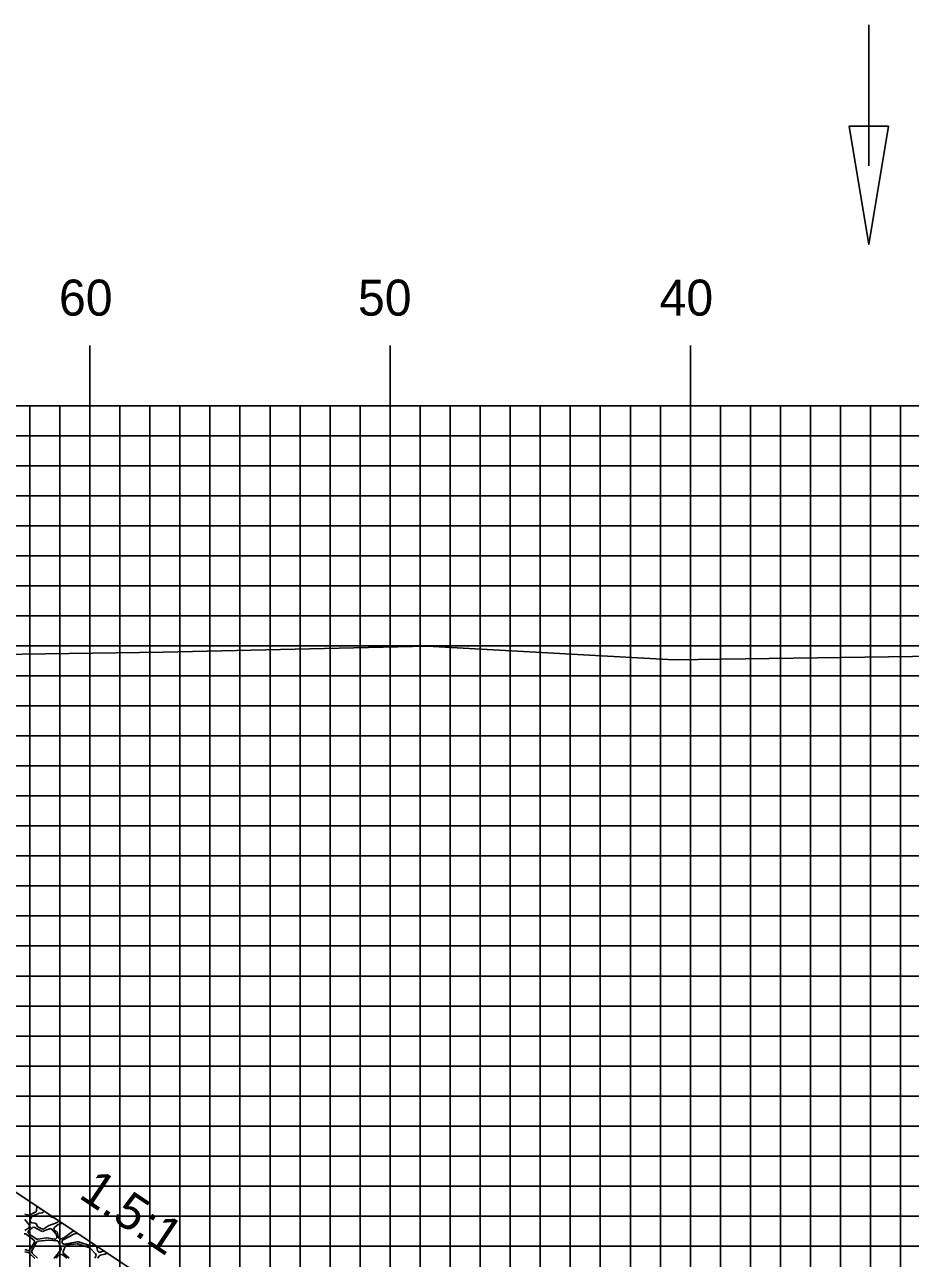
# Model space of a CAD drawing. Extents: x 1770055 to 1770398, y 442591 to 442811.
# Drawn here: x 1770158.36 to 1770187.85, y 442635.26 to 442676.36 of the extents above; entities that cross this region are included whole.
import ezdxf

# ---------------------------------------------------------------- set-up
doc = ezdxf.new("R2010")
doc.units = 0
for name, color, linetype in [('ANNOTATION', 7, 'Continuous'), ('D_Drainage_Ditch_Line', 7, 'Continuous'), ('D_Roadway_Centerline', 7, 'Continuous'), ('D_Roadway_SlopeLines', 7, 'Continuous'), ('GRUBBING IN FILL', 7, 'Continuous'), ('H_V ANNOTATION', 7, 'Continuous'), ('MAJOR', 7, 'Continuous'), ('MINOR', 7, 'Continuous'), ('S_Roadway_Centerline', 7, 'Continuous')]:
    doc.layers.add(name, color=color, linetype=linetype)

msp = doc.modelspace()

# ---------------------------------------------------------------- linework, layer by layer
at = {"layer": 'D_Drainage_Ditch_Line'}
msp.add_line((1770186.466, 442671.659), (1770186.466, 442676.358), dxfattribs=at)
msp.add_lwpolyline([(1770187.122, 442672.972), (1770185.81, 442672.972), (1770186.466, 442669.035)], close=True, dxfattribs=at)
at = {"layer": 'D_Roadway_Centerline'}
msp.add_lwpolyline([(1770129.303, 442654.95), (1770129.452, 442654.939), (1770130.553, 442654.854), (1770130.77, 442654.801), (1770131.803, 442654.548), (1770132.952, 442654.073), (1770133.053, 442654.031), (1770134.303, 442653.303), (1770134.304, 442653.302), (1770162.371, 442634.591), (1770186.354, 442618.602), (1770187.025, 442618.77), (1770190.354, 442619.602), (1770200.03, 442622.022), (1770200.528, 442622.146), (1770208.528, 442622.466), (1770220.528, 442622.706), (1770227.293, 442622.571), (1770232.528, 442622.466), (1770240.528, 442622.146), (1770241.369, 442621.936), (1770250.701, 442619.602), (1770250.702, 442619.602), (1770253.913, 442618.8)], dxfattribs=at)
at = {"layer": 'D_Roadway_SlopeLines'}
msp.add_lwpolyline([(1770186.354, 442618.602), (1770134.303, 442653.303), (1770133.053, 442654.031), (1770131.803, 442654.548), (1770130.553, 442654.854), (1770129.303, 442654.95)], dxfattribs=at)
at = {"layer": 'GRUBBING IN FILL'}
for p, q in [((1770158.76, 442636.998), (1770158.747, 442636.851)), ((1770158.491, 442636.7), (1770158.358, 442636.735)), ((1770158.358, 442636.556), (1770158.504, 442636.378)), ((1770158.711, 442636.797), (1770158.541, 442636.706)), ((1770158.543, 442636.537), (1770158.589, 442636.642)), ((1770158.625, 442636.677), (1770158.818, 442636.758)), ((1770158.836, 442636.762), (1770158.927, 442636.774)), ((1770158.871, 442636.913), (1770158.864, 442636.929)), ((1770158.922, 442636.891), (1770158.9, 442636.892)), ((1770158.962, 442636.789), (1770159, 442636.822)), ((1770159.2, 442636.705), (1770159.205, 442636.68)), ((1770159.258, 442636.628), (1770159.342, 442636.61)), ((1770158.492, 442636.28), (1770158.358, 442636.182)), ((1770158.498, 442636.184), (1770158.624, 442636.286)), ((1770158.701, 442636.431), (1770158.599, 442636.442)), ((1770158.701, 442636.292), (1770158.918, 442636.166)), ((1770158.762, 442636.366), (1770158.761, 442636.371)), ((1770158.931, 442636.244), (1770158.798, 442636.314)), ((1770158.978, 442636.162), (1770159.188, 442636.245)), ((1770159.159, 442636.349), (1770158.999, 442636.247)), ((1770159.44, 442636.45), (1770159.173, 442636.356)), ((1770159.265, 442636.226), (1770159.403, 442636.065)), ((1770159.355, 442636.287), (1770159.44, 442636.364)), ((1770159.412, 442636.153), (1770159.369, 442636.176)), ((1770159.451, 442636.371), (1770159.609, 442636.432)), ((1770159.95, 442636.15), (1770159.688, 442635.953)), ((1770160.012, 442636.163), (1770159.993, 442636.164)), ((1770158.403, 442636.066), (1770158.658, 442635.869)), ((1770158.744, 442635.908), (1770158.502, 442636.075)), ((1770158.676, 442635.781), (1770158.544, 442635.554)), ((1770158.749, 442635.799), (1770158.6, 442635.507)), ((1770159.081, 442635.937), (1770158.792, 442635.897)), ((1770159.143, 442635.87), (1770158.803, 442635.836)), ((1770159.35, 442635.899), (1770159.1, 442635.937)), ((1770159.441, 442635.837), (1770159.158, 442635.869)), ((1770159.418, 442636.033), (1770159.428, 442635.979)), ((1770159.466, 442636.015), (1770159.447, 442636.107)), ((1770159.487, 442635.955), (1770159.469, 442636.005)), ((1770159.567, 442635.612), (1770159.497, 442635.794)), ((1770159.667, 442635.942), (1770159.571, 442635.912)), ((1770159.603, 442635.802), (1770159.609, 442635.779)), ((1770159.991, 442636.068), (1770159.637, 442635.881)), ((1770159.687, 442635.73), (1770160.115, 442635.807)), ((1770160.101, 442635.743), (1770159.762, 442635.704)), ((1770160.131, 442636.085), (1770160.017, 442636.075)), ((1770160.523, 442635.604), (1770160.131, 442635.739)), ((1770160.147, 442635.805), (1770160.561, 442635.681)), ((1770160.647, 442635.733), (1770160.649, 442635.739)), ((1770158.466, 442635.522), (1770158.358, 442635.553)), ((1770158.358, 442635.471), (1770158.475, 442635.451)), ((1770158.509, 442635.434), (1770158.686, 442635.269)), ((1770158.612, 442635.427), (1770158.78, 442635.26)), ((1770159.352, 442635.28), (1770159.557, 442635.545)), ((1770159.465, 442635.341), (1770159.41, 442635.26)), ((1770159.567, 442635.387), (1770159.502, 442635.368)), ((1770159.762, 442635.26), (1770159.632, 442635.373)), ((1770159.705, 442635.659), (1770159.644, 442635.491)), ((1770159.663, 442635.417), (1770159.839, 442635.26)), ((1770160.718, 442635.409), (1770160.55, 442635.586)), ((1770160.699, 442635.26), (1770160.731, 442635.335)), ((1770160.787, 442635.518), (1770160.753, 442635.669)), ((1770160.787, 442635.26), (1770160.849, 442635.339)), ((1770161.001, 442635.504), (1770160.872, 442635.467)), ((1770160.884, 442635.363), (1770161.026, 442635.401)), ((1770161.031, 442635.403), (1770161.11, 442635.431)), ((1770159.329, 442635.26), (1770159.34, 442635.269))]:
    msp.add_line(p, q, dxfattribs=at)
for centre, major_axis, start_param, end_param in [((1770158.509, 442636.766), (0, -0.0683), 6.025862, 6.773143), ((1770158.652, 442636.614), (0, 0.0683), 0.394791, 1.157466), ((1770158.679, 442636.857), (0, -0.0683), 0.489957, 1.480136), ((1770158.844, 442636.694), (0, 0.0683), 0.124355, 0.394791), ((1770158.902, 442636.926), (0, -0.0342), 5.10718, 6.225111), ((1770158.918, 442636.841), (0, -0.0683), 0.124355, 0.704494), ((1770159.044, 442636.77), (0, 0.0683), 0.484122, 0.704494), ((1770159.272, 442636.695), (0, -0.0683), 4.928939, 6.08014), ((1770158.541, 442636.131), (0, -0.0683), 3.820255, 5.679955), ((1770158.451, 442636.335), (0, 0.0683), 3.773738, 5.401291), ((1770158.606, 442636.51), (0, -0.0683), 4.299059, 6.17752), ((1770158.667, 442636.233), (0, 0.0683), 5.75839, 6.961848), ((1770158.693, 442636.363), (0, 0.0683), 4.831818, 6.17752), ((1770158.829, 442636.374), (0, -0.0683), 4.831818, 5.797153), ((1770158.953, 442636.225), (0, -0.0683), 5.75839, 6.659146), ((1770158.962, 442636.304), (0, -0.0683), 5.797153, 6.853569), ((1770159.196, 442636.292), (0, 0.0683), 0.338698, 0.570383), ((1770159.213, 442636.181), (0, 0.0683), 5.421015, 6.659146), ((1770159.401, 442636.236), (0, -0.0683), 3.878249, 5.800672), ((1770159.381, 442636.093), (0, 0.0683), 4.915434, 5.800672), ((1770159.417, 442636.515), (0, 0.0683), 3.480291, 4.716793), ((1770159.463, 442636.339), (0, 0.0342), 0.369906, 0.736656), ((1770159.991, 442636.096), (0, 0.0683), 6.255795, 6.928761), ((1770158.361, 442636.012), (0, 0.0683), 0.046753, 0.339293), ((1770158.361, 442636.012), (0, 0.0683), 5.625297, 6.329939), ((1770158.617, 442635.815), (0, 0.0683), 4.185762, 5.625297), ((1770158.783, 442635.964), (0, -0.0683), 5.679955, 6.421825), ((1770158.81, 442635.768), (0, 0.0683), 0.097727, 1.099019), ((1770159.09, 442635.869), (0, 0.0683), 6.135336, 6.421825), ((1770159.15, 442635.802), (0, 0.0683), 6.170034, 6.380912), ((1770159.361, 442635.967), (0, 0.0683), 2.993743, 4.892242), ((1770159.351, 442636.021), (0, 0.0683), 4.892242, 5.421015), ((1770159.434, 442635.769), (0, 0.0683), 5.07759, 6.170034), ((1770159.533, 442636.028), (0, -0.0683), 4.915434, 5.053368), ((1770159.551, 442635.978), (0, -0.0683), 5.053368, 6.584804), ((1770159.669, 442635.82), (0, 0.0683), 0.485227, 1.841743), ((1770159.675, 442635.797), (0, -0.0683), 4.983336, 6.460411), ((1770159.647, 442636.007), (0, -0.0683), 0.301619, 0.645576), ((1770160.022, 442636.007), (0, 0.0683), 0.083141, 0.485227), ((1770160.109, 442635.675), (0, 0.0683), 5.950458, 6.397059), ((1770160.127, 442635.74), (0, 0.0683), 5.991139, 6.460411), ((1770160.58, 442635.746), (0, -0.0683), 5.991139, 7.656876), ((1770158.485, 442635.588), (0, -0.0683), 6.004886, 7.327354), ((1770158.463, 442635.384), (0, 0.0683), 5.534807, 6.110994), ((1770158.661, 442635.476), (0, 0.0683), 1.099019, 2.356194), ((1770159.522, 442635.302), (0, 0.0683), 0.294235, 0.97362), ((1770159.503, 442635.587), (0, -0.0683), 0.911486, 1.935998), ((1770159.587, 442635.322), (0, 0.0683), 5.565745, 6.57742), ((1770159.708, 442635.467), (0, 0.0683), 1.223118, 2.412764), ((1770159.769, 442635.636), (0, 0.0683), 0.113874, 1.223118), ((1770160.5, 442635.539), (0, 0.0683), 5.472885, 5.950458), ((1770160.669, 442635.362), (0, -0.0683), 1.163165, 2.331293), ((1770160.853, 442635.533), (0, -0.0683), 4.928939, 6.561485), ((1770160.902, 442635.297), (0, 0.0683), 0.266252, 0.90675), ((1770161.008, 442635.467), (0, -0.0683), 0.266252, 0.343024), ((1770158.64, 442635.219), (0, 0.0683), 5.35086, 5.534807), ((1770159.298, 442635.322), (0, -0.0683), 0.674741, 0.911486)]:
    msp.add_ellipse(centre, major_axis=major_axis, ratio=0.99895, start_param=start_param, end_param=end_param, dxfattribs=at)
at = {"layer": 'MAJOR'}
for p, q in [((1770160.528, 442665.669), (1770160.528, 442663.665)), ((1770170.528, 442665.669), (1770170.528, 442663.665)), ((1770180.528, 442665.669), (1770180.528, 442663.665)), ((1770080.528, 442663.665), (1770360.528, 442663.665)), ((1770080.528, 442663.665), (1770360.528, 442663.665)), ((1770160.528, 442608.665), (1770160.528, 442663.665)), ((1770170.528, 442608.665), (1770170.528, 442663.665)), ((1770180.528, 442608.665), (1770180.528, 442663.665)), ((1770080.528, 442658.665), (1770360.528, 442658.665)), ((1770080.528, 442653.665), (1770360.528, 442653.665)), ((1770080.528, 442648.665), (1770360.528, 442648.665)), ((1770080.528, 442643.665), (1770360.528, 442643.665)), ((1770080.528, 442638.665), (1770360.528, 442638.665))]:
    msp.add_line(p, q, dxfattribs=at)
at = {"layer": 'MINOR'}
for p, q in [((1770158.528, 442608.665), (1770158.528, 442663.665)), ((1770159.528, 442608.665), (1770159.528, 442663.665)), ((1770161.528, 442608.665), (1770161.528, 442663.665)), ((1770162.528, 442608.665), (1770162.528, 442663.665)), ((1770163.528, 442608.665), (1770163.528, 442663.665)), ((1770164.528, 442608.665), (1770164.528, 442663.665)), ((1770165.528, 442608.665), (1770165.528, 442663.665)), ((1770166.528, 442608.665), (1770166.528, 442663.665)), ((1770167.528, 442608.665), (1770167.528, 442663.665)), ((1770168.528, 442608.665), (1770168.528, 442663.665)), ((1770169.528, 442608.665), (1770169.528, 442663.665)), ((1770171.528, 442608.665), (1770171.528, 442663.665)), ((1770172.528, 442608.665), (1770172.528, 442663.665)), ((1770173.528, 442608.665), (1770173.528, 442663.665)), ((1770174.528, 442608.665), (1770174.528, 442663.665)), ((1770175.528, 442608.665), (1770175.528, 442663.665)), ((1770176.528, 442608.665), (1770176.528, 442663.665)), ((1770177.528, 442608.665), (1770177.528, 442663.665)), ((1770178.528, 442608.665), (1770178.528, 442663.665)), ((1770179.528, 442608.665), (1770179.528, 442663.665)), ((1770181.528, 442608.665), (1770181.528, 442663.665)), ((1770182.528, 442608.665), (1770182.528, 442663.665)), ((1770183.528, 442608.665), (1770183.528, 442663.665)), ((1770184.528, 442608.665), (1770184.528, 442663.665)), ((1770185.528, 442608.665), (1770185.528, 442663.665)), ((1770186.528, 442608.665), (1770186.528, 442663.665)), ((1770187.528, 442608.665), (1770187.528, 442663.665)), ((1770080.528, 442662.665), (1770360.528, 442662.665)), ((1770080.528, 442661.665), (1770360.528, 442661.665)), ((1770080.528, 442660.665), (1770360.528, 442660.665)), ((1770080.528, 442659.665), (1770360.528, 442659.665)), ((1770080.528, 442657.665), (1770360.528, 442657.665)), ((1770080.528, 442656.665), (1770360.528, 442656.665)), ((1770080.528, 442655.665), (1770360.528, 442655.665)), ((1770080.528, 442654.665), (1770360.528, 442654.665)), ((1770080.528, 442652.665), (1770360.528, 442652.665)), ((1770080.528, 442651.665), (1770360.528, 442651.665)), ((1770080.528, 442650.665), (1770360.528, 442650.665)), ((1770080.528, 442649.665), (1770360.528, 442649.665)), ((1770080.528, 442647.665), (1770360.528, 442647.665)), ((1770080.528, 442646.665), (1770360.528, 442646.665)), ((1770080.528, 442645.665), (1770360.528, 442645.665)), ((1770080.528, 442644.665), (1770360.528, 442644.665)), ((1770080.528, 442642.665), (1770360.528, 442642.665)), ((1770080.528, 442641.665), (1770360.528, 442641.665)), ((1770080.528, 442640.665), (1770360.528, 442640.665)), ((1770080.528, 442639.665), (1770360.528, 442639.665)), ((1770080.528, 442637.665), (1770360.528, 442637.665)), ((1770080.528, 442636.665), (1770360.528, 442636.665)), ((1770080.528, 442635.665), (1770360.528, 442635.665))]:
    msp.add_line(p, q, dxfattribs=at)
at = {"layer": 'S_Roadway_Centerline'}
msp.add_lwpolyline([(1770080.528, 442654.157), (1770085.186, 442654.318), (1770094.979, 442654.295), (1770097.217, 442654.304), (1770100.488, 442654.483), (1770114.303, 442654.9), (1770130.273, 442654.953), (1770131.884, 442654.971), (1770133.085, 442655.012), (1770144.868, 442655.54), (1770153.558, 442655.315), (1770162.971, 442655.45), (1770171.758, 442655.657), (1770179.977, 442655.201), (1770191.894, 442655.367), (1770192.415, 442655.364), (1770199.74, 442655.199), (1770205.48, 442654.814), (1770211.859, 442654.469), (1770223.576, 442654.243), (1770230.798, 442654.178), (1770247.848, 442652.967), (1770251.575, 442652.677)], dxfattribs=at)

# ---------------------------------------------------------------- texts
at = {"layer": 'ANNOTATION'}
msp.add_text('1.5:1', height=1.2, rotation=326.3096, dxfattribs=at).set_placement((1770160.118, 442637.297))
at = {"layer": 'H_V ANNOTATION'}
for s, p in [('60', (1770159.5, 442666.665)), ('50', (1770169.457, 442666.665)), ('40', (1770179.5, 442666.665))]:
    msp.add_text(s, height=1.2, dxfattribs=at).set_placement(p)

doc.saveas('drawing.dxf')
